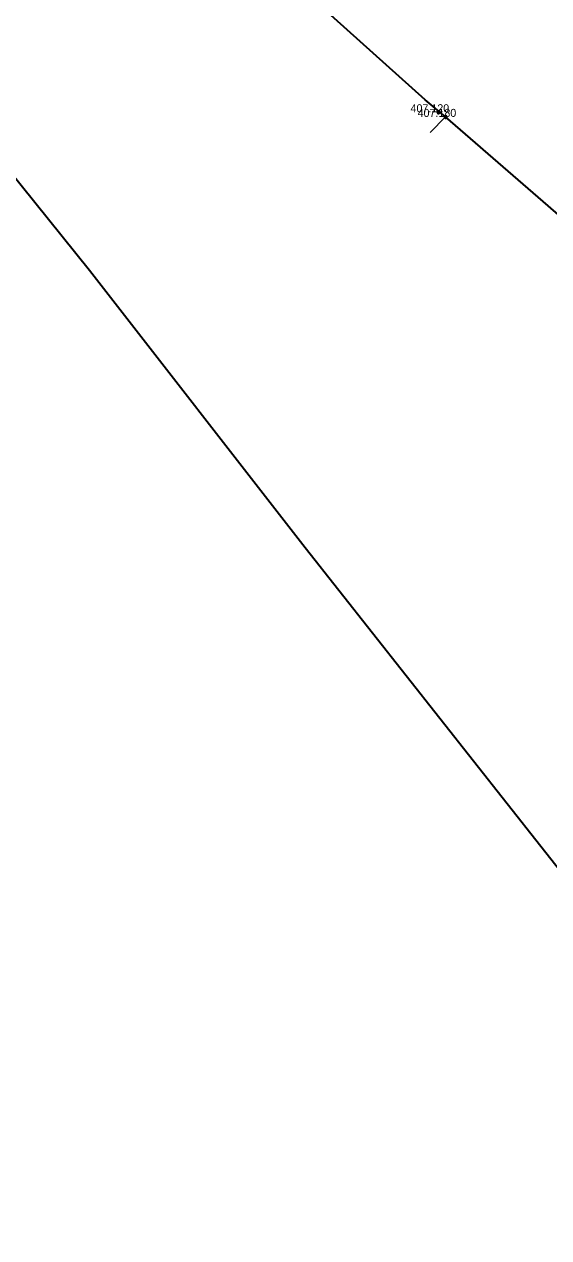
# Model space of a CAD drawing. Extents: x -873619 to -867639, y -1015082 to -1012326.
# Drawn here: x -868249.8 to -868171.2, y -1012871.4 to -1012689.5 of the extents above; entities that cross this region are included whole.
import ezdxf

# ---------------------------------------------------------------- set-up
doc = ezdxf.new("R2010")
doc.units = 0
doc.header["$LTSCALE"] = 0.44
for name, color, linetype, lineweight in [('1', 7, 'Continuous', 13), ('12', 7, 'Continuous', 13), ('21', 7, 'Continuous', 35), ('3', 7, 'Continuous', 25)]:
    doc.layers.add(name, color=color, linetype=linetype, lineweight=lineweight)

msp = doc.modelspace()

# ---------------------------------------------------------------- linework, layer by layer
at = {"layer": '1', "lineweight": 35}
msp.add_lwpolyline([(-868094.808, -1012782.506), (-868128.65, -1012753.034), (-868142.107, -1012741.315), (-868163.447, -1012723.713), (-868165.629, -1012721.604), (-868186.647, -1012703.368), (-868189.69, -1012700.802), (-868224.291, -1012669.746), (-868245.779, -1012651.034), (-868246.236, -1012651.387)], dxfattribs=at)
at = {"layer": '1'}
for points in [[(-868187.477, -1012702.67), (-868187.483, -1012702.618), (-868187.5, -1012702.568), (-868187.529, -1012702.524), (-868187.566, -1012702.487), (-868187.611, -1012702.46), (-868187.661, -1012702.443), (-868187.714, -1012702.439), (-868187.766, -1012702.446), (-868187.815, -1012702.465), (-868187.858, -1012702.494), (-868187.894, -1012702.533), (-868187.92, -1012702.578), (-868187.936, -1012702.629), (-868187.939, -1012702.681), (-868187.931, -1012702.733), (-868187.911, -1012702.782), (-868187.88, -1012702.825), (-868187.841, -1012702.859), (-868187.795, -1012702.885), (-868187.744, -1012702.899), (-868187.691, -1012702.901), (-868187.64, -1012702.891), (-868187.592, -1012702.87), (-868187.549, -1012702.839), (-868187.515, -1012702.798), (-868187.491, -1012702.752), (-868187.478, -1012702.701)], [(-868187.507, -1012702.67), (-868187.513, -1012702.621), (-868187.53, -1012702.575), (-868187.558, -1012702.535), (-868187.595, -1012702.503), (-868187.639, -1012702.481), (-868187.687, -1012702.47), (-868187.736, -1012702.47), (-868187.782, -1012702.483), (-868187.826, -1012702.507), (-868187.862, -1012702.54), (-868187.889, -1012702.581), (-868187.905, -1012702.628), (-868187.909, -1012702.677), (-868187.902, -1012702.725), (-868187.883, -1012702.77), (-868187.853, -1012702.81), (-868187.815, -1012702.841), (-868187.771, -1012702.861), (-868187.723, -1012702.871), (-868187.674, -1012702.869), (-868187.627, -1012702.854), (-868187.584, -1012702.829), (-868187.549, -1012702.795), (-868187.524, -1012702.753), (-868187.51, -1012702.706)], [(-868187.537, -1012702.67), (-868187.543, -1012702.625), (-868187.559, -1012702.583), (-868187.588, -1012702.548), (-868187.624, -1012702.521), (-868187.666, -1012702.504), (-868187.711, -1012702.499), (-868187.755, -1012702.505), (-868187.797, -1012702.524), (-868187.831, -1012702.552), (-868187.858, -1012702.589), (-868187.875, -1012702.631), (-868187.879, -1012702.676), (-868187.872, -1012702.721), (-868187.853, -1012702.762), (-868187.824, -1012702.796), (-868187.787, -1012702.822), (-868187.744, -1012702.838), (-868187.699, -1012702.841), (-868187.654, -1012702.833), (-868187.614, -1012702.813), (-868187.58, -1012702.784), (-868187.554, -1012702.746), (-868187.54, -1012702.703)], [(-868187.567, -1012702.67), (-868187.571, -1012702.629), (-868187.59, -1012702.592), (-868187.617, -1012702.561), (-868187.652, -1012702.54), (-868187.692, -1012702.529), (-868187.733, -1012702.531), (-868187.772, -1012702.544), (-868187.806, -1012702.568), (-868187.831, -1012702.6), (-868187.846, -1012702.638), (-868187.848, -1012702.679), (-868187.841, -1012702.719), (-868187.821, -1012702.755), (-868187.792, -1012702.784), (-868187.755, -1012702.803), (-868187.715, -1012702.811), (-868187.674, -1012702.807), (-868187.636, -1012702.792), (-868187.603, -1012702.766), (-868187.581, -1012702.732), (-868187.568, -1012702.693)], [(-868187.597, -1012702.67), (-868187.602, -1012702.634), (-868187.62, -1012702.602), (-868187.646, -1012702.577), (-868187.679, -1012702.562), (-868187.716, -1012702.559), (-868187.75, -1012702.567), (-868187.782, -1012702.587), (-868187.804, -1012702.615), (-868187.818, -1012702.649), (-868187.818, -1012702.686), (-868187.807, -1012702.721), (-868187.786, -1012702.75), (-868187.755, -1012702.771), (-868187.721, -1012702.781), (-868187.684, -1012702.779), (-868187.65, -1012702.765), (-868187.623, -1012702.742), (-868187.603, -1012702.71), (-868187.597, -1012702.675)], [(-868187.627, -1012702.67), (-868187.632, -1012702.639), (-868187.649, -1012702.613), (-868187.674, -1012702.596), (-868187.705, -1012702.589), (-868187.736, -1012702.593), (-868187.763, -1012702.61), (-868187.781, -1012702.634), (-868187.789, -1012702.665), (-868187.785, -1012702.695), (-868187.77, -1012702.723), (-868187.745, -1012702.742), (-868187.716, -1012702.751), (-868187.684, -1012702.748), (-868187.657, -1012702.734), (-868187.637, -1012702.71), (-868187.627, -1012702.681)], [(-868187.657, -1012702.67), (-868187.662, -1012702.646), (-868187.679, -1012702.628), (-868187.701, -1012702.619), (-868187.726, -1012702.622), (-868187.747, -1012702.636), (-868187.758, -1012702.658), (-868187.758, -1012702.683), (-868187.745, -1012702.704), (-868187.726, -1012702.718), (-868187.701, -1012702.721), (-868187.678, -1012702.712), (-868187.662, -1012702.694)], [(-868187.687, -1012702.67), (-868187.692, -1012702.655), (-868187.706, -1012702.649), (-868187.722, -1012702.653), (-868187.728, -1012702.667), (-868187.725, -1012702.682), (-868187.712, -1012702.691), (-868187.696, -1012702.688), (-868187.687, -1012702.676)], [(-868186.416, -1012703.368), (-868186.422, -1012703.316), (-868186.439, -1012703.266), (-868186.468, -1012703.222), (-868186.505, -1012703.185), (-868186.55, -1012703.158), (-868186.6, -1012703.141), (-868186.653, -1012703.137), (-868186.705, -1012703.144), (-868186.754, -1012703.163), (-868186.797, -1012703.192), (-868186.833, -1012703.231), (-868186.859, -1012703.276), (-868186.875, -1012703.327), (-868186.878, -1012703.379), (-868186.87, -1012703.431), (-868186.85, -1012703.48), (-868186.819, -1012703.523), (-868186.78, -1012703.557), (-868186.734, -1012703.583), (-868186.683, -1012703.597), (-868186.63, -1012703.599), (-868186.579, -1012703.589), (-868186.531, -1012703.568), (-868186.488, -1012703.537), (-868186.454, -1012703.496), (-868186.43, -1012703.45), (-868186.418, -1012703.399)], [(-868186.446, -1012703.368), (-868186.452, -1012703.319), (-868186.469, -1012703.273), (-868186.497, -1012703.233), (-868186.534, -1012703.201), (-868186.578, -1012703.179), (-868186.626, -1012703.168), (-868186.675, -1012703.168), (-868186.722, -1012703.181), (-868186.765, -1012703.205), (-868186.801, -1012703.238), (-868186.828, -1012703.279), (-868186.844, -1012703.326), (-868186.848, -1012703.375), (-868186.841, -1012703.423), (-868186.822, -1012703.468), (-868186.792, -1012703.508), (-868186.754, -1012703.539), (-868186.71, -1012703.559), (-868186.662, -1012703.569), (-868186.613, -1012703.567), (-868186.566, -1012703.552), (-868186.523, -1012703.527), (-868186.489, -1012703.493), (-868186.463, -1012703.451), (-868186.449, -1012703.404)], [(-868186.476, -1012703.368), (-868186.482, -1012703.323), (-868186.499, -1012703.281), (-868186.527, -1012703.246), (-868186.563, -1012703.219), (-868186.605, -1012703.202), (-868186.65, -1012703.197), (-868186.695, -1012703.203), (-868186.736, -1012703.222), (-868186.771, -1012703.25), (-868186.798, -1012703.287), (-868186.814, -1012703.329), (-868186.818, -1012703.374), (-868186.811, -1012703.419), (-868186.792, -1012703.46), (-868186.763, -1012703.494), (-868186.726, -1012703.52), (-868186.683, -1012703.536), (-868186.638, -1012703.539), (-868186.593, -1012703.531), (-868186.553, -1012703.511), (-868186.519, -1012703.482), (-868186.493, -1012703.444), (-868186.479, -1012703.401)], [(-868186.506, -1012703.368), (-868186.511, -1012703.327), (-868186.529, -1012703.29), (-868186.556, -1012703.259), (-868186.591, -1012703.238), (-868186.631, -1012703.227), (-868186.672, -1012703.229), (-868186.711, -1012703.242), (-868186.745, -1012703.266), (-868186.77, -1012703.298), (-868186.785, -1012703.336), (-868186.788, -1012703.377), (-868186.78, -1012703.417), (-868186.76, -1012703.453), (-868186.731, -1012703.482), (-868186.694, -1012703.501), (-868186.654, -1012703.509), (-868186.613, -1012703.505), (-868186.575, -1012703.49), (-868186.543, -1012703.464), (-868186.52, -1012703.43), (-868186.507, -1012703.391)], [(-868186.536, -1012703.368), (-868186.541, -1012703.332), (-868186.559, -1012703.3), (-868186.585, -1012703.275), (-868186.619, -1012703.26), (-868186.655, -1012703.257), (-868186.69, -1012703.265), (-868186.721, -1012703.285), (-868186.744, -1012703.313), (-868186.757, -1012703.347), (-868186.757, -1012703.384), (-868186.746, -1012703.419), (-868186.725, -1012703.448), (-868186.695, -1012703.469), (-868186.66, -1012703.479), (-868186.623, -1012703.477), (-868186.589, -1012703.463), (-868186.562, -1012703.44), (-868186.543, -1012703.408), (-868186.536, -1012703.373)], [(-868186.566, -1012703.368), (-868186.571, -1012703.337), (-868186.588, -1012703.311), (-868186.614, -1012703.294), (-868186.644, -1012703.287), (-868186.675, -1012703.291), (-868186.702, -1012703.308), (-868186.72, -1012703.332), (-868186.728, -1012703.363), (-868186.724, -1012703.393), (-868186.709, -1012703.421), (-868186.684, -1012703.44), (-868186.655, -1012703.449), (-868186.624, -1012703.446), (-868186.596, -1012703.432), (-868186.576, -1012703.408), (-868186.566, -1012703.379)], [(-868186.596, -1012703.368), (-868186.601, -1012703.344), (-868186.618, -1012703.326), (-868186.641, -1012703.317), (-868186.665, -1012703.32), (-868186.686, -1012703.334), (-868186.697, -1012703.356), (-868186.697, -1012703.381), (-868186.684, -1012703.402), (-868186.665, -1012703.416), (-868186.64, -1012703.419), (-868186.617, -1012703.41), (-868186.601, -1012703.392)], [(-868186.626, -1012703.368), (-868186.631, -1012703.353), (-868186.646, -1012703.347), (-868186.661, -1012703.351), (-868186.668, -1012703.365), (-868186.664, -1012703.38), (-868186.651, -1012703.389), (-868186.636, -1012703.386), (-868186.626, -1012703.374)]]:
    msp.add_lwpolyline(points, close=True, dxfattribs=at)
at = {"layer": '12'}
for points in [[(-868187.477, -1012702.67), (-868187.483, -1012702.618), (-868187.5, -1012702.568), (-868187.529, -1012702.524), (-868187.566, -1012702.487), (-868187.611, -1012702.46), (-868187.661, -1012702.443), (-868187.714, -1012702.439), (-868187.766, -1012702.446), (-868187.815, -1012702.465), (-868187.858, -1012702.494), (-868187.894, -1012702.533), (-868187.92, -1012702.578), (-868187.936, -1012702.629), (-868187.939, -1012702.681), (-868187.931, -1012702.733), (-868187.911, -1012702.782), (-868187.88, -1012702.825), (-868187.841, -1012702.859), (-868187.795, -1012702.885), (-868187.744, -1012702.899), (-868187.691, -1012702.901), (-868187.64, -1012702.891), (-868187.592, -1012702.87), (-868187.549, -1012702.839), (-868187.515, -1012702.798), (-868187.491, -1012702.752), (-868187.478, -1012702.701)], [(-868187.507, -1012702.67), (-868187.513, -1012702.621), (-868187.53, -1012702.575), (-868187.558, -1012702.535), (-868187.595, -1012702.503), (-868187.639, -1012702.481), (-868187.687, -1012702.47), (-868187.736, -1012702.47), (-868187.782, -1012702.483), (-868187.826, -1012702.507), (-868187.862, -1012702.54), (-868187.889, -1012702.581), (-868187.905, -1012702.628), (-868187.909, -1012702.677), (-868187.902, -1012702.725), (-868187.883, -1012702.77), (-868187.853, -1012702.81), (-868187.815, -1012702.841), (-868187.771, -1012702.861), (-868187.723, -1012702.871), (-868187.674, -1012702.869), (-868187.627, -1012702.854), (-868187.584, -1012702.829), (-868187.549, -1012702.795), (-868187.524, -1012702.753), (-868187.51, -1012702.706)], [(-868187.537, -1012702.67), (-868187.543, -1012702.625), (-868187.559, -1012702.583), (-868187.588, -1012702.548), (-868187.624, -1012702.521), (-868187.666, -1012702.504), (-868187.711, -1012702.499), (-868187.755, -1012702.505), (-868187.797, -1012702.524), (-868187.831, -1012702.552), (-868187.858, -1012702.589), (-868187.875, -1012702.631), (-868187.879, -1012702.676), (-868187.872, -1012702.721), (-868187.853, -1012702.762), (-868187.824, -1012702.796), (-868187.787, -1012702.822), (-868187.744, -1012702.838), (-868187.699, -1012702.841), (-868187.654, -1012702.833), (-868187.614, -1012702.813), (-868187.58, -1012702.784), (-868187.554, -1012702.746), (-868187.54, -1012702.703)], [(-868187.567, -1012702.67), (-868187.571, -1012702.629), (-868187.59, -1012702.592), (-868187.617, -1012702.561), (-868187.652, -1012702.54), (-868187.692, -1012702.529), (-868187.733, -1012702.531), (-868187.772, -1012702.544), (-868187.806, -1012702.568), (-868187.831, -1012702.6), (-868187.846, -1012702.638), (-868187.848, -1012702.679), (-868187.841, -1012702.719), (-868187.821, -1012702.755), (-868187.792, -1012702.784), (-868187.755, -1012702.803), (-868187.715, -1012702.811), (-868187.674, -1012702.807), (-868187.636, -1012702.792), (-868187.603, -1012702.766), (-868187.581, -1012702.732), (-868187.568, -1012702.693)], [(-868187.597, -1012702.67), (-868187.602, -1012702.634), (-868187.62, -1012702.602), (-868187.646, -1012702.577), (-868187.679, -1012702.562), (-868187.716, -1012702.559), (-868187.75, -1012702.567), (-868187.782, -1012702.587), (-868187.804, -1012702.615), (-868187.818, -1012702.649), (-868187.818, -1012702.686), (-868187.807, -1012702.721), (-868187.786, -1012702.75), (-868187.755, -1012702.771), (-868187.721, -1012702.781), (-868187.684, -1012702.779), (-868187.65, -1012702.765), (-868187.623, -1012702.742), (-868187.603, -1012702.71), (-868187.597, -1012702.675)], [(-868187.627, -1012702.67), (-868187.632, -1012702.639), (-868187.649, -1012702.613), (-868187.674, -1012702.596), (-868187.705, -1012702.589), (-868187.736, -1012702.593), (-868187.763, -1012702.61), (-868187.781, -1012702.634), (-868187.789, -1012702.665), (-868187.785, -1012702.695), (-868187.77, -1012702.723), (-868187.745, -1012702.742), (-868187.716, -1012702.751), (-868187.684, -1012702.748), (-868187.657, -1012702.734), (-868187.637, -1012702.71), (-868187.627, -1012702.681)], [(-868187.657, -1012702.67), (-868187.662, -1012702.646), (-868187.679, -1012702.628), (-868187.701, -1012702.619), (-868187.726, -1012702.622), (-868187.747, -1012702.636), (-868187.758, -1012702.658), (-868187.758, -1012702.683), (-868187.745, -1012702.704), (-868187.726, -1012702.718), (-868187.701, -1012702.721), (-868187.678, -1012702.712), (-868187.662, -1012702.694)], [(-868187.687, -1012702.67), (-868187.692, -1012702.655), (-868187.706, -1012702.649), (-868187.722, -1012702.653), (-868187.728, -1012702.667), (-868187.725, -1012702.682), (-868187.712, -1012702.691), (-868187.696, -1012702.688), (-868187.687, -1012702.676)]]:
    msp.add_lwpolyline(points, close=True, dxfattribs=at)
at = {"layer": '21'}
msp.add_lwpolyline([(-868376.717, -1012555.154), (-868316.566, -1012631.217), (-868240.045, -1012726.354), (-868207.711, -1012767.909), (-868167.337, -1012819.086), (-868122.692, -1012851.556), (-868075.313, -1012871.422), (-868043.707, -1012866.643), (-868020.287, -1012856.898)], dxfattribs=at)
at = {"layer": '3'}
msp.add_line((-868186.647, -1012703.368), (-868188.944, -1012705.715), dxfattribs=at)

# ---------------------------------------------------------------- texts
at = {"layer": '1'}
for s, p in [('407.120 ', (-868191.908, -1012702.67)), ('407.180 ', (-868190.847, -1012703.368))]:
    msp.add_text(s, height=1.2, dxfattribs=at).set_placement(p)

doc.saveas('drawing.dxf')
